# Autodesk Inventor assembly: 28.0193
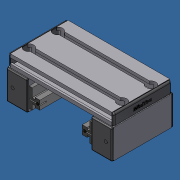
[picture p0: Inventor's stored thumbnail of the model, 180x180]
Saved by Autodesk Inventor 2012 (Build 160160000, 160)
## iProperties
Created: 2007-06
Part Number: 28.0193
Document SubType Name: Assembly
Designer: Andy Moles
Description: SLIDE LWN 32X45-90
Author: Andy Moles
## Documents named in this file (8)
- C:\Andys Backup Data\ANDY'S INVENTOR\INVENTOR LIBRARIES\PARTS LIBRARY\READY FOR USE MODULES LG\28.0193 SLIDE LWN 32X45-90.iam
- C:\Andys Backup Data\ANDY'S INVENTOR\INVENTOR LIBRARIES\PARTS LIBRARY\READY FOR USE MODULES LG\SUBCOMPONENTS\28.0126 SLIDE 45X32.ipt
- C:\Andys Backup Data\ANDY'S INVENTOR\INVENTOR LIBRARIES\PARTS LIBRARY\COMPONENTS LG\22.1095 SLIDE RAIL LN.iam
- C:\Andys Backup Data\ANDY'S INVENTOR\INVENTOR LIBRARIES\PARTS LIBRARY\FASTENING ELEMENTS\SCREWS CAP\21.1200 M8X16.ipt
- C:\Andys Backup Data\ANDY'S INVENTOR\INVENTOR LIBRARIES\PARTS LIBRARY\FASTENING ELEMENTS\NUTS\21.1351 M8 SQUARE NUT.ipt
- C:\Andys Backup Data\ANDY'S INVENTOR\INVENTOR LIBRARIES\PARTS LIBRARY\READY FOR USE MODULES LG\SUBCOMPONENTS\28.0224 SLIDE LWN 32X45-90 90X19.ipt
- C:\Andys Backup Data\ANDY'S INVENTOR\INVENTOR LIBRARIES\PARTS LIBRARY\END CAPS\22.1014_1 END CAP 90X19 GRAY.ipt
- C:\Andys Backup Data\ANDY'S INVENTOR\INVENTOR LIBRARIES\PARTS LIBRARY\END CAPS\22.1003_1 END CAP 45x32 Z Gray.iam
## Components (19 placed, 7 different names)
1. 28.0224 SLIDE LWN 32X45-90 90X19:1 — Mate:1, Mate:2, Flush:1, Mate:3, Flush:2, Flush:3, Mate:4, Flush:4, Flush:5, Flush:18, Flush:19, Insert:1, Insert:2, Insert:3, Insert:4, Insert:5, Insert:6, Insert:7, Insert:8, Mate:15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
2. 28.0126 SLIDE 45X32:1 — Mate:3, Flush:2, Flush:3, Mate:11, Mate:12, Mate:17, Flush:23, Flush:24, Mate:20, Flush:29, Flush:30
3. 28.0126 SLIDE 45X32:2 — Mate:4, Flush:4, Flush:5, Mate:13, Mate:14, Mate:18, Flush:25, Flush:26, Mate:19, Flush:27, Flush:28
4. 22.1014_1 END CAP 90X19 GRAY:1 — Mate:16, Flush:21, Flush:22
5. 22.1014_1 END CAP 90X19 GRAY:2 — Mate:15, Flush:20
6. 22.1095 SLIDE RAIL LN:1 [sub-assembly] — Mate:11, Flush:18, Mate:12
7. 22.1095 SLIDE RAIL LN:3 [sub-assembly] — Mate:13, Flush:19, Mate:14
8. 21.1200 M8 x 16:1 — Insert:1
9. 21.1200 M8 x 16:2 — Insert:2
10. 21.1200 M8 x 16:3 — Insert:3
11. 21.1200 M8 x 16:4 — Insert:4
12. 21.1351 M8 SQUARE NUT:1 — Insert:5
13. 21.1351 M8 SQUARE NUT:2 — Insert:6
14. 21.1351 M8 SQUARE NUT:3 — Insert:8
15. 21.1351 M8 SQUARE NUT:4 — Insert:7
16. 22.1003_1 END CAP 45x32 Z Gray:1 [sub-assembly] — Mate:17, Flush:23, Flush:24
17. 22.1003_1 END CAP 45x32 Z Gray:2 [sub-assembly] — Mate:18, Flush:25, Flush:26
18. 22.1003_1 END CAP 45x32 Z Gray:3 [sub-assembly] — Mate:19, Flush:27, Flush:28
19. 22.1003_1 END CAP 45x32 Z Gray:4 [sub-assembly] — Mate:20, Flush:29, Flush:30
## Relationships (40: Flush 18, Mate 14, Insert 8)
- Mate:1: 28.0224 SLIDE LWN 32X45-90 90X19:1
- Mate:2: 28.0224 SLIDE LWN 32X45-90 90X19:1
- Flush:1: 28.0224 SLIDE LWN 32X45-90 90X19:1
- Mate:3: 28.0224 SLIDE LWN 32X45-90 90X19:1 ↔ 28.0126 SLIDE 45X32:1
- Flush:2: 28.0224 SLIDE LWN 32X45-90 90X19:1 ↔ 28.0126 SLIDE 45X32:1
- Flush:3: 28.0224 SLIDE LWN 32X45-90 90X19:1 ↔ 28.0126 SLIDE 45X32:1
- Mate:4: 28.0224 SLIDE LWN 32X45-90 90X19:1 ↔ 28.0126 SLIDE 45X32:2
- Flush:4: 28.0224 SLIDE LWN 32X45-90 90X19:1 ↔ 28.0126 SLIDE 45X32:2
- Flush:5: 28.0224 SLIDE LWN 32X45-90 90X19:1 ↔ 28.0126 SLIDE 45X32:2
- Mate:11: 28.0126 SLIDE 45X32:1 ↔ 22.1095 SLIDE RAIL LN:1
- Flush:18: 28.0224 SLIDE LWN 32X45-90 90X19:1 ↔ 22.1095 SLIDE RAIL LN:1
- Mate:12: 28.0126 SLIDE 45X32:1 ↔ 22.1095 SLIDE RAIL LN:1
- Mate:13: 28.0126 SLIDE 45X32:2 ↔ 22.1095 SLIDE RAIL LN:3
- Flush:19: 28.0224 SLIDE LWN 32X45-90 90X19:1 ↔ 22.1095 SLIDE RAIL LN:3
- Mate:14: 28.0126 SLIDE 45X32:2 ↔ 22.1095 SLIDE RAIL LN:3
- Insert:1: 28.0224 SLIDE LWN 32X45-90 90X19:1 ↔ 21.1200 M8 x 16:1
- Insert:2: 28.0224 SLIDE LWN 32X45-90 90X19:1 ↔ 21.1200 M8 x 16:2
- Insert:3: 28.0224 SLIDE LWN 32X45-90 90X19:1 ↔ 21.1200 M8 x 16:3
- Insert:4: 28.0224 SLIDE LWN 32X45-90 90X19:1 ↔ 21.1200 M8 x 16:4
- Insert:5: 28.0224 SLIDE LWN 32X45-90 90X19:1 ↔ 21.1351 M8 SQUARE NUT:1
- Insert:6: 28.0224 SLIDE LWN 32X45-90 90X19:1 ↔ 21.1351 M8 SQUARE NUT:2
- Insert:7: 28.0224 SLIDE LWN 32X45-90 90X19:1 ↔ 21.1351 M8 SQUARE NUT:4
- Insert:8: 28.0224 SLIDE LWN 32X45-90 90X19:1 ↔ 21.1351 M8 SQUARE NUT:3
- Mate:15: 28.0224 SLIDE LWN 32X45-90 90X19:1 ↔ 22.1014_1 END CAP 90X19 GRAY:2
- Flush:20: 28.0224 SLIDE LWN 32X45-90 90X19:1 ↔ 22.1014_1 END CAP 90X19 GRAY:2
- Mate:16: 28.0224 SLIDE LWN 32X45-90 90X19:1 ↔ 22.1014_1 END CAP 90X19 GRAY:1
- Flush:21: 28.0224 SLIDE LWN 32X45-90 90X19:1 ↔ 22.1014_1 END CAP 90X19 GRAY:1
- Flush:22: 28.0224 SLIDE LWN 32X45-90 90X19:1 ↔ 22.1014_1 END CAP 90X19 GRAY:1
- Mate:17: 28.0126 SLIDE 45X32:1 ↔ 22.1003_1 END CAP 45x32 Z Gray:1
- Flush:23: 28.0126 SLIDE 45X32:1 ↔ 22.1003_1 END CAP 45x32 Z Gray:1
- Flush:24: 28.0126 SLIDE 45X32:1 ↔ 22.1003_1 END CAP 45x32 Z Gray:1
- Mate:18: 28.0126 SLIDE 45X32:2 ↔ 22.1003_1 END CAP 45x32 Z Gray:2
- Flush:25: 28.0126 SLIDE 45X32:2 ↔ 22.1003_1 END CAP 45x32 Z Gray:2
- Flush:26: 28.0126 SLIDE 45X32:2 ↔ 22.1003_1 END CAP 45x32 Z Gray:2
- Mate:19: 28.0126 SLIDE 45X32:2 ↔ 22.1003_1 END CAP 45x32 Z Gray:3
- Flush:27: 28.0126 SLIDE 45X32:2 ↔ 22.1003_1 END CAP 45x32 Z Gray:3
- Flush:28: 28.0126 SLIDE 45X32:2 ↔ 22.1003_1 END CAP 45x32 Z Gray:3
- Mate:20: 28.0126 SLIDE 45X32:1 ↔ 22.1003_1 END CAP 45x32 Z Gray:4
- Flush:29: 28.0126 SLIDE 45X32:1 ↔ 22.1003_1 END CAP 45x32 Z Gray:4
- Flush:30: 28.0126 SLIDE 45X32:1 ↔ 22.1003_1 END CAP 45x32 Z Gray:4
